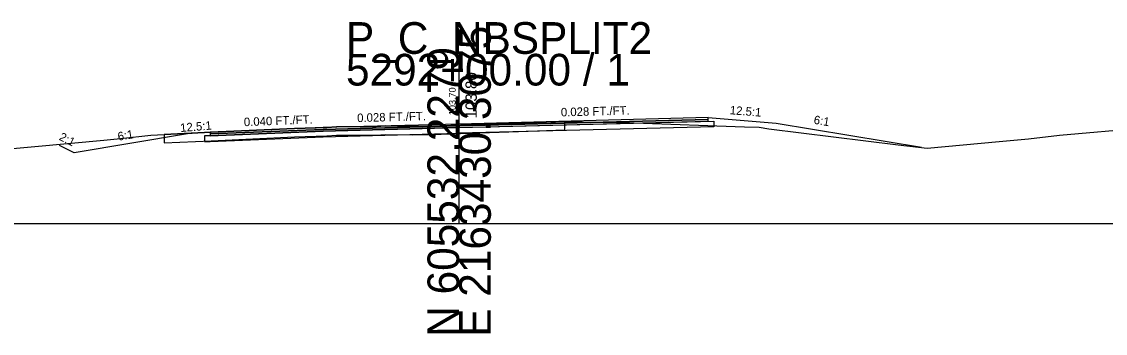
# Model space of a CAD drawing. Extents: x -26 to 1303, y -10 to 12038.
# Drawn here: x 111.3 to 207.1, y 6490.3 to 6517.8 of the extents above; entities that cross this region are included whole.
import ezdxf

# ---------------------------------------------------------------- set-up
doc = ezdxf.new("R2010")
doc.units = 0
for name, color, linetype in [('RD_GPK_XS_Cell', 7, 'Continuous'), ('RD_XS_Base', 7, 'Continuous'), ('RD_XS_ExGround', 7, 'Continuous'), ('RD_XS_ExPaveRet', 7, 'Continuous'), ('RD_XS_Greenside', 7, 'Continuous'), ('RD_XS_Pave', 7, 'Continuous'), ('RD_XS_PaveOvlay_CP', 7, 'Continuous'), ('RD_XS_TieSlope', 7, 'Continuous'), ('RD_XS_TX_Elev_EX', 7, 'Continuous'), ('RD_XS_TX_Elev_PR', 7, 'Continuous'), ('RD_XS_TX_ShdSlope', 7, 'Continuous'), ('RD_XS_TX_Slope', 7, 'Continuous')]:
    doc.layers.add(name, color=color, linetype=linetype)

msp = doc.modelspace()

# ---------------------------------------------------------------- linework, layer by layer
at = {"layer": 'RD_GPK_XS_Cell'}
for p, q in [((150, 6500), (150, 6515)), ((0, 6500), (150, 6500)), ((150, 6500), (300, 6500))]:
    msp.add_line(p, q, dxfattribs=at)
at = {"layer": 'RD_XS_Base'}
for p, q in [((150, 6508.478), (172.5, 6509.063)), ((172, 6509.05), (172, 6509.05)), ((172, 6509.05), (172, 6509.05)), ((172, 6509.05), (172, 6509.05)), ((172.5, 6509.063), (172.5, 6508.563)), ((172.5, 6509.03), (172.5, 6509.03)), ((138, 6508.166), (128, 6507.766)), ((150, 6508.478), (138, 6508.166)), ((138, 6508.166), (138, 6508.166)), ((138, 6507.666), (150, 6507.978)), ((150, 6507.978), (150, 6508.637)), ((150, 6508.637), (150, 6508.637)), ((150, 6508.637), (150, 6508.637)), ((150, 6508.637), (150, 6508.478)), ((172.5, 6508.563), (150, 6507.978)), ((150, 6508.478), (150, 6508.478)), ((150, 6507.978), (150, 6508.478)), ((150, 6508.478), (150, 6508.478)), ((150, 6508.478), (150, 6508.478)), ((150, 6507.978), (150, 6507.978)), ((172, 6508.55), (172, 6508.55)), ((172, 6508.55), (172, 6508.55)), ((128, 6507.766), (127.5, 6507.746)), ((127.5, 6507.746), (127.5, 6507.746)), ((127.5, 6507.746), (127.5, 6507.246)), ((127.5, 6507.246), (128, 6507.266)), ((128, 6507.766), (128, 6507.766)), ((128, 6507.266), (138, 6507.666)), ((128, 6507.266), (128, 6507.266)), ((138, 6507.666), (138, 6507.666))]:
    msp.add_line(p, q, dxfattribs=at)
at = {"layer": 'RD_XS_ExGround'}
msp.add_lwpolyline([(109.259, 6506.507), (118.602, 6507.377), (120.093, 6507.512), (122.765, 6507.815), (123.925, 6507.876), (128.086, 6508.065), (135.447, 6508.412), (138.314, 6508.501), (139.176, 6508.55), (142.657, 6508.572), (143.497, 6508.634), (145.898, 6508.588), (147.55, 6508.611), (156.113, 6508.912), (159.329, 6509.026), (165.476, 6508.912), (175.217, 6508.563), (176.512, 6508.509), (177.374, 6508.377), (188.785, 6506.95), (191.35, 6506.66), (197.7, 6507.245), (200.293, 6507.501), (203.059, 6507.813), (210.425, 6508.473)], dxfattribs=at)
at = {"layer": 'RD_XS_ExPaveRet'}
for points in [[(159.329, 6509.026), (156.113, 6508.912), (156.113, 6508.912), (147.55, 6508.611), (145.898, 6508.588), (145.898, 6508.588), (145.898, 6508.588), (143.497, 6508.634), (143.497, 6508.634), (142.657, 6508.572), (142.657, 6508.572), (139.176, 6508.55), (139.176, 6508.55), (138.314, 6508.501), (138.314, 6508.501), (135.447, 6508.412), (135.447, 6508.412), (135.447, 6508.412), (135.447, 6508.412), (128.086, 6508.065), (128.086, 6508.065), (123.925, 6507.876), (123.925, 6507.876), (123.925, 6507.876), (123.925, 6507.126), (123.925, 6507.126), (128.086, 6507.315), (128.086, 6507.315), (135.447, 6507.662), (135.447, 6507.662), (135.447, 6507.662), (135.447, 6507.662), (138.314, 6507.751), (138.314, 6507.751), (139.176, 6507.8), (139.176, 6507.8), (142.657, 6507.822), (142.657, 6507.822), (143.497, 6507.884), (143.497, 6507.884), (145.898, 6507.838), (145.898, 6507.838), (145.898, 6507.838), (147.55, 6507.861), (156.113, 6508.162), (156.113, 6508.162), (159.329, 6508.276), (159.329, 6508.276), (159.329, 6509.026), (159.329, 6509.026), (159.329, 6509.026)], [(159.329, 6509.026), (156.113, 6508.912), (147.55, 6508.611), (145.898, 6508.588), (143.497, 6508.634), (142.657, 6508.572), (139.176, 6508.55), (138.314, 6508.501), (135.447, 6508.412), (128.086, 6508.065), (123.925, 6507.876), (123.925, 6507.876), (123.925, 6507.126), (123.925, 6507.126), (128.086, 6507.315), (135.447, 6507.662), (138.314, 6507.751), (139.176, 6507.8), (142.657, 6507.822), (143.497, 6507.884), (145.898, 6507.838), (147.55, 6507.861), (156.113, 6508.162), (159.329, 6508.276), (159.329, 6509.026)]]:
    msp.add_lwpolyline(points, dxfattribs=at)
at = {"layer": 'RD_XS_Greenside'}
for p, q in [((178, 6508.888), (190.85, 6506.746)), ((126, 6507.924), (116, 6506.257)), ((116, 6506.257), (114.7, 6506.907))]:
    msp.add_line(p, q, dxfattribs=at)
at = {"layer": 'RD_XS_Pave'}
for p, q in [((172, 6509.368), (150, 6508.796)), ((172, 6509.209), (150, 6508.637)), ((150, 6508.637), (172, 6509.209)), ((150, 6508.478), (172, 6509.05)), ((172, 6509.209), (172, 6509.368)), ((172, 6509.368), (172, 6509.368)), ((172, 6509.368), (172, 6509.368)), ((172, 6509.368), (172, 6509.368)), ((172, 6509.05), (172, 6509.209)), ((172, 6509.209), (172, 6509.209)), ((172, 6509.209), (172, 6509.209)), ((172, 6509.209), (172, 6509.209)), ((172, 6509.209), (172, 6509.209)), ((172, 6509.209), (172, 6509.209)), ((172, 6509.05), (172, 6509.05)), ((172, 6509.05), (172, 6509.05)), ((138, 6508.484), (128, 6508.084)), ((128, 6507.925), (138, 6508.325)), ((138, 6508.325), (128, 6507.925)), ((128, 6507.766), (138, 6508.166)), ((128, 6508.084), (128, 6508.084)), ((128, 6508.084), (128, 6507.925)), ((128, 6507.925), (128, 6507.925)), ((128, 6507.925), (128, 6507.766)), ((150, 6508.796), (138, 6508.484)), ((138, 6508.325), (150, 6508.637)), ((150, 6508.637), (138, 6508.325)), ((138, 6508.484), (138, 6508.484)), ((138, 6508.166), (150, 6508.478)), ((138, 6508.325), (138, 6508.325)), ((138, 6508.325), (138, 6508.325)), ((138, 6508.166), (138, 6508.166)), ((150, 6508.796), (150, 6508.796)), ((150, 6508.637), (150, 6508.637)), ((150, 6508.637), (150, 6508.637)), ((150, 6508.637), (150, 6508.478)), ((150, 6508.637), (150, 6508.637)), ((150, 6508.478), (150, 6508.637)), ((150, 6508.637), (150, 6508.637)), ((150, 6508.637), (150, 6508.637)), ((150, 6508.478), (150, 6508.478)), ((150, 6508.478), (150, 6508.478))]:
    msp.add_line(p, q, dxfattribs=at)
at = {"layer": 'RD_XS_PaveOvlay_CP'}
for p, q in [((172, 6509.368), (150, 6508.796)), ((172, 6509.368), (172, 6509.368)), ((172, 6509.368), (172, 6509.368)), ((138, 6508.484), (128, 6508.084)), ((150, 6508.796), (138, 6508.484)), ((138, 6508.484), (138, 6508.484)), ((150, 6508.796), (150, 6508.796))]:
    msp.add_line(p, q, dxfattribs=at)
at = {"layer": 'RD_XS_TieSlope'}
for p, q in [((172, 6509.368), (178, 6508.888)), ((128, 6508.084), (126, 6507.924))]:
    msp.add_line(p, q, dxfattribs=at)

# ---------------------------------------------------------------- texts
at = {"layer": 'RD_GPK_XS_Cell'}
for s, p in [('P_C_NBSPLIT2', (140, 6515)), ('5292+00.00 / 1', (140, 6512.2))]:
    msp.add_text(s, height=2.8, dxfattribs=at).set_placement(p)
for s, p in [('E 2163430.3075', (152.8, 6490)), ('N 605532.2279', (150, 6490))]:
    msp.add_text(s, height=2.8, rotation=90, dxfattribs=at).set_placement(p)
at = {"layer": 'RD_XS_TX_Elev_EX'}
msp.add_text('103.70', height=0.6, rotation=90, dxfattribs=at).set_placement((149.697, 6509.585))
at = {"layer": 'RD_XS_TX_Elev_PR'}
msp.add_text('103.80', height=1, rotation=90, dxfattribs=at).set_placement((151.563, 6509.288))
at = {"layer": 'RD_XS_TX_ShdSlope'}
for rotation, p in [(355.42608, (173.893, 6509.667)), (4.57392, (125.384, 6508.09))]:
    msp.add_text('12.5:1', height=0.75, rotation=rotation, dxfattribs=at).set_placement(p)
at = {"layer": 'RD_XS_TX_Slope'}
for s, rotation, p in [('0.028 FT./FT.', 1.60386, (140.999, 6508.966)), ('0.028 FT./FT.', 1.60386, (158.999, 6509.47)), ('0.040 FT./FT.', 2.29061, (130.995, 6508.602)), ('6:1', 350.53768, (181.29, 6508.828)), ('2:1', 333.43495, (114.588, 6507.424)), ('6:1', 9.46418, (119.893, 6507.322))]:
    msp.add_text(s, height=0.75, rotation=rotation, dxfattribs=at).set_placement(p)

doc.saveas('drawing.dxf')
